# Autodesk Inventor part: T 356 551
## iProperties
Company: Mayer & Mueller Schaltgeräte AG
Created: 2005-10
Part Number: T 356 551
Material: 1.4301
Document SubType Name: Modeling
Designer: I.Baliuc
Manufacturer: Standard
Standards Organization: Custom
Description: Bolzen
Density: 7.86 g/cm^3
Mass: 36.196 g
Surface Area: 18.3549 cm^2
Volume: 4.60508 cm^3
Abmessung: Skt SW19
HalbzeugNorm: DIN 176
Zweck: Schalthebel Trenner
Author: T.Messerschmitt
Revision Number: 356551
Keywords: 380078
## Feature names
1. Basis1
2. Extrusion1
3. Extrusion2
4. Fase1 [Chamfer]
